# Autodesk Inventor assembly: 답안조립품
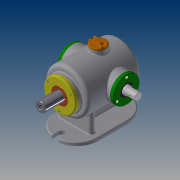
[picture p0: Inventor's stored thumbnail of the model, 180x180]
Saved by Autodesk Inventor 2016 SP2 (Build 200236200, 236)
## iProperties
Created: 2018-02
Part Number: 답안조립품
Document SubType Name: Assembly
Designer: Administrator
Mass: 7551.89 g
Surface Area: 3901.69 cm^2
Volume: 1791.93 cm^3
Density: 4.2144 g/cm^3
Author: Administrator
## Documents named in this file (16)
- D:\380207V1014\답안조립품.iam
- D:\380207V1014\본체.ipt
- D:\380207V1014\가변스프링.ipt
- D:\380207V1014\베어링 6205.ipt
- 베어링 6205.ipt
- D:\380207V1014\본체커버.ipt
- D:\380207V1014\볼트 M4.ipt
- D:\380207V1014\부시.ipt
- D:\380207V1014\상부 캡.ipt
- D:\380207V1014\슬라이드 커버.ipt
- D:\380207V1014\슬라이드.ipt
- D:\380207V1014\오일실.ipt
- 오일실.ipt
- D:\380207V1014\축 커버-1.ipt
- D:\380207V1014\축 커버-2.ipt
- D:\380207V1014\편심축.ipt
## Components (1 placed, 1 different names)
1. 가변스프링:1
